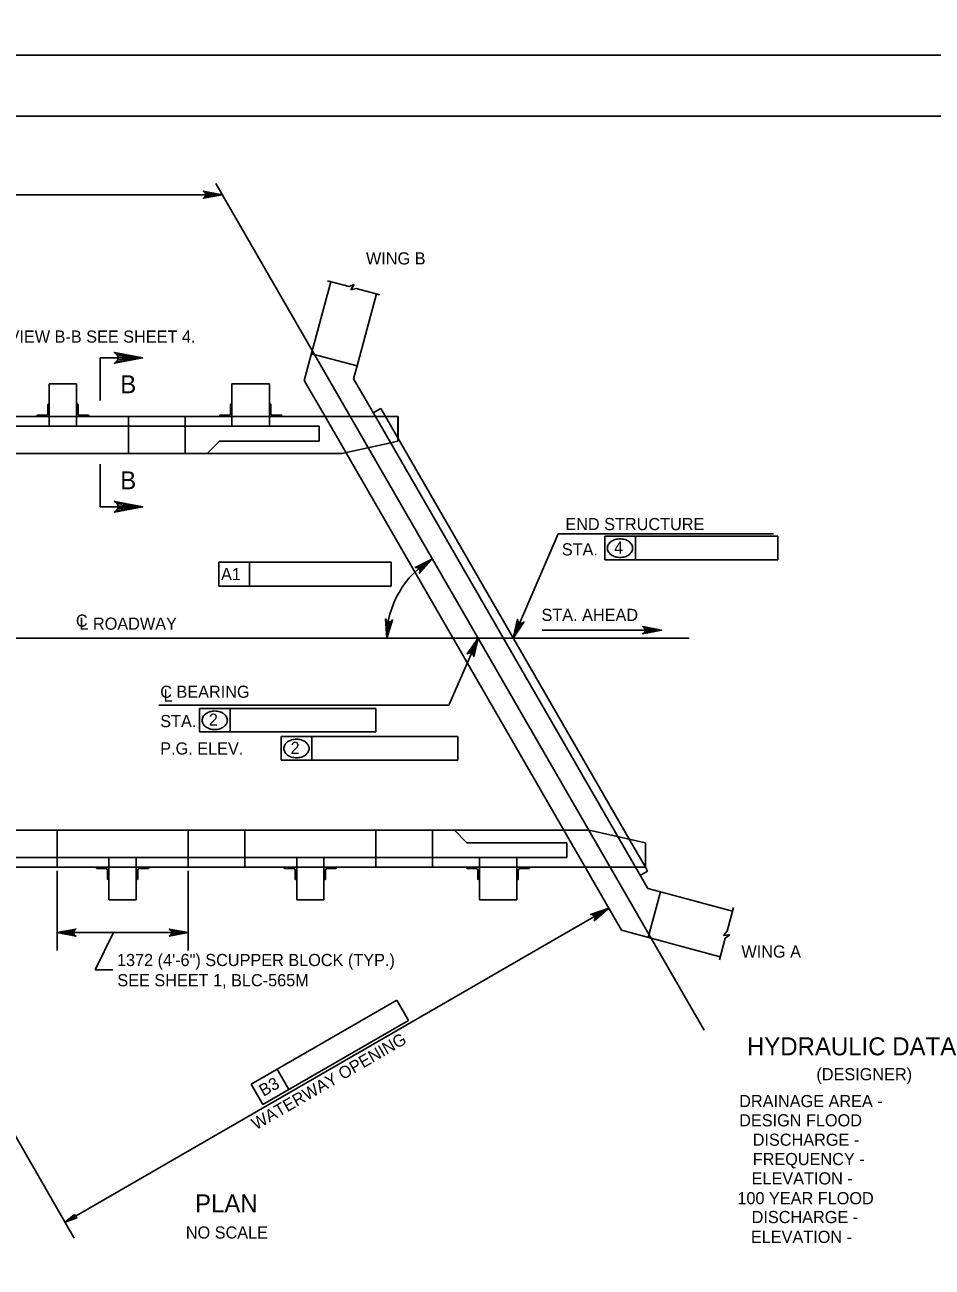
# Model space of a CAD drawing. Extents: x 638175 to 640495, y 294277 to 298435.
# Drawn here: x 638663 to 638887, y 296948.4 to 297255 of the extents above; entities that cross this region are included whole.
import ezdxf

# ---------------------------------------------------------------- set-up
doc = ezdxf.new("R2010")
doc.units = 0
for name, color, linetype in [('2', 7, 'Continuous'), ('3', 7, 'Continuous'), ('4', 7, 'Continuous'), ('PLT-BNDY', 7, 'Continuous')]:
    doc.layers.add(name, color=color, linetype=linetype)

msp = doc.modelspace()

# ---------------------------------------------------------------- linework, layer by layer
at = {"layer": '2'}
for p, q in [((638475.46, 297232.46), (639261.46, 297232.46)), ((638732.01, 297167.17), (638738.55, 297191.57)), ((638745.03, 297170.77), (638749.79, 297188.56)), ((638681.61, 297172.77), (638681.61, 297162.29)), ((638681.61, 297172.77), (638692.1, 297172.77)), ((638745.03, 297170.77), (638733.78, 297173.78)), ((638744.18, 297167.62), (638745.03, 297170.77)), ((638675.77, 297166.36), (638669.04, 297166.36)), ((638675.77, 297166.36), (638669.04, 297166.36)), ((638675.77, 297166.36), (638669.04, 297166.36)), ((638669.04, 297166.36), (638669.04, 297155.88)), ((638675.77, 297166.36), (638675.77, 297155.88)), ((638723.39, 297166.36), (638714.15, 297166.36)), ((638714.15, 297166.36), (638714.15, 297155.88)), ((638723.39, 297166.36), (638723.39, 297155.88)), ((638732.01, 297167.17), (638737.15, 297158.27)), ((638744.18, 297167.62), (638749.58, 297158.27)), ((638668.68, 297161.18), (638668.68, 297159)), ((638668.86, 297161.36), (638669.04, 297161.36)), ((638669.04, 297161.36), (638669.04, 297158.27)), ((638675.95, 297161.36), (638675.77, 297161.36)), ((638675.77, 297161.36), (638675.77, 297158.27)), ((638676.13, 297161.18), (638676.13, 297159)), ((638713.79, 297161.18), (638713.79, 297159)), ((638713.97, 297161.36), (638714.15, 297161.36)), ((638714.15, 297161.36), (638714.15, 297158.27)), ((638723.57, 297161.36), (638723.39, 297161.36)), ((638723.39, 297161.36), (638723.39, 297158.27)), ((638723.75, 297161.18), (638723.75, 297159)), ((638750.87, 297160.29), (638749.03, 297159.22)), ((638750.87, 297160.29), (638752.04, 297158.27)), ((638543.27, 297158.27), (638755.15, 297158.27)), ((638608.04, 297158.27), (638755.13, 297158.27)), ((638667.79, 297158.27), (638664.7, 297158.27)), ((638665.95, 297158.45), (638665.95, 297158.27)), ((638669.04, 297158.27), (638665.95, 297158.27)), ((638666.13, 297158.63), (638668.32, 297158.63)), ((638677.02, 297158.27), (638667.79, 297158.27)), ((638677.02, 297158.27), (638667.79, 297158.27)), ((638675.77, 297158.27), (638669.04, 297158.27)), ((638675.77, 297158.27), (638678.86, 297158.27)), ((638678.68, 297158.63), (638676.5, 297158.63)), ((638677.02, 297158.27), (638680.12, 297158.27)), ((638678.86, 297158.45), (638678.86, 297158.27)), ((638688.58, 297158.27), (638688.58, 297149.15)), ((638702.6, 297158.27), (638702.6, 297149.15)), ((638711.06, 297158.45), (638711.06, 297158.27)), ((638714.15, 297158.27), (638711.06, 297158.27)), ((638711.24, 297158.63), (638713.42, 297158.63)), ((638723.39, 297158.27), (638714.15, 297158.27)), ((638723.39, 297158.27), (638726.48, 297158.27)), ((638726.3, 297158.63), (638724.12, 297158.63)), ((638726.48, 297158.45), (638726.48, 297158.27)), ((638737.15, 297158.27), (638801.34, 297047.1)), ((638749.58, 297158.27), (638813.77, 297047.1)), ((638752.04, 297158.27), (638755.15, 297152.88)), ((638755.13, 297152.89), (638755.13, 297158.27)), ((638755.13, 297158.27), (638755.13, 297152.24)), ((638755.15, 297152.89), (638755.15, 297158.27)), ((638735.71, 297155.88), (638607.87, 297155.88)), ((638735.71, 297155.88), (638735.71, 297152.24)), ((638707.98, 297149.15), (638711.07, 297152.24)), ((638735.71, 297152.24), (638711.07, 297152.24)), ((638752.96, 297151.76), (638741.28, 297149.15)), ((638755.13, 297152.24), (638752.96, 297151.76)), ((638755.15, 297152.88), (638812.49, 297053.57)), ((638590.42, 297149.15), (638741.28, 297149.15)), ((638707.98, 297149.15), (638691.82, 297149.15)), ((638681.61, 297136.04), (638681.61, 297146.53)), ((638681.61, 297136.04), (638692.1, 297136.04)), ((638651.51, 297056.22), (638667.67, 297056.22)), ((638651.51, 297056.22), (638802.37, 297056.22)), ((638670.96, 297047.1), (638670.96, 297056.22)), ((638703.3, 297047.1), (638703.3, 297056.22)), ((638717.33, 297047.1), (638717.33, 297056.22)), ((638769.07, 297056.22), (638748.29, 297056.22)), ((638749.67, 297047.1), (638749.67, 297056.22)), ((638763.69, 297047.1), (638763.69, 297056.22)), ((638769.07, 297056.22), (638772.16, 297053.13)), ((638814.05, 297053.61), (638802.37, 297056.22)), ((638796.8, 297053.13), (638772.16, 297053.13)), ((638796.8, 297049.49), (638796.8, 297053.13)), ((638812.49, 297053.57), (638816.22, 297047.1)), ((638816.22, 297053.13), (638814.05, 297053.61)), ((638816.22, 297047.1), (638816.22, 297053.13)), ((638816.22, 297052.48), (638816.22, 297047.1)), ((638623.78, 297049.49), (638668.96, 297049.49)), ((638669.05, 297047.1), (638645.34, 297047.1)), ((638796.8, 297049.49), (638668.96, 297049.49)), ((638669.13, 297047.1), (638816.22, 297047.1)), ((638680.68, 297046.92), (638680.68, 297047.1)), ((638683.77, 297047.1), (638680.68, 297047.1)), ((638680.86, 297046.73), (638683.04, 297046.73)), ((638683.77, 297039.01), (638683.77, 297049.49)), ((638690.5, 297047.1), (638683.77, 297047.1)), ((638683.77, 297044.01), (638683.77, 297047.1)), ((638690.5, 297039.01), (638690.5, 297049.49)), ((638690.5, 297044.01), (638690.5, 297047.1)), ((638690.5, 297047.1), (638693.59, 297047.1)), ((638693.4, 297046.73), (638691.22, 297046.73)), ((638693.59, 297046.92), (638693.59, 297047.1)), ((638727.04, 297046.92), (638727.04, 297047.1)), ((638730.13, 297047.1), (638727.04, 297047.1)), ((638727.22, 297046.73), (638729.4, 297046.73)), ((638738.11, 297047.1), (638728.88, 297047.1)), ((638730.13, 297039.01), (638730.13, 297049.49)), ((638736.86, 297047.1), (638730.13, 297047.1)), ((638730.13, 297044.01), (638730.13, 297047.1)), ((638736.86, 297039.01), (638736.86, 297049.49)), ((638736.86, 297044.01), (638736.86, 297047.1)), ((638736.86, 297047.1), (638739.95, 297047.1)), ((638739.77, 297046.73), (638737.59, 297046.73)), ((638739.95, 297046.92), (638739.95, 297047.1)), ((638772.15, 297046.92), (638772.15, 297047.1)), ((638775.24, 297047.1), (638772.15, 297047.1)), ((638772.33, 297046.73), (638774.51, 297046.73)), ((638775.24, 297039.01), (638775.24, 297049.49)), ((638784.48, 297047.1), (638775.24, 297047.1)), ((638775.24, 297044.01), (638775.24, 297047.1)), ((638784.48, 297039.01), (638784.48, 297049.49)), ((638784.48, 297044.01), (638784.48, 297047.1)), ((638784.48, 297047.1), (638787.57, 297047.1)), ((638787.39, 297046.73), (638785.21, 297046.73)), ((638787.57, 297046.92), (638787.57, 297047.1)), ((638810.33, 297031.52), (638801.34, 297047.1)), ((638813.77, 297047.1), (638816.8, 297041.84)), ((638816.22, 297047.1), (638816.78, 297046.14)), ((638816.22, 297047.1), (638816.78, 297046.14)), ((638683.4, 297044.19), (638683.4, 297046.37)), ((638683.59, 297044.01), (638683.77, 297044.01)), ((638690.68, 297044.01), (638690.5, 297044.01)), ((638690.86, 297044.19), (638690.86, 297046.37)), ((638729.77, 297044.19), (638729.77, 297046.37)), ((638729.95, 297044.01), (638730.13, 297044.01)), ((638737.04, 297044.01), (638736.86, 297044.01)), ((638737.22, 297044.19), (638737.22, 297046.37)), ((638774.88, 297044.19), (638774.88, 297046.37)), ((638775.06, 297044.01), (638775.24, 297044.01)), ((638784.66, 297044.01), (638784.48, 297044.01)), ((638784.84, 297044.19), (638784.84, 297046.37)), ((638816.78, 297046.14), (638814.93, 297045.07)), ((638816.8, 297041.84), (638819.95, 297041)), ((638819.95, 297041), (638816.94, 297029.75)), ((638819.95, 297041), (638837.74, 297036.23)), ((638690.5, 297039.01), (638683.77, 297039.01)), ((638736.86, 297039.01), (638730.13, 297039.01)), ((638736.86, 297039.01), (638730.13, 297039.01)), ((638784.48, 297039.01), (638775.24, 297039.01)), ((638810.33, 297031.52), (638834.73, 297024.98))]:
    msp.add_line(p, q, dxfattribs=at)
for points in [[(638692.1, 297172.77), (638685.1, 297171.46), (638685.64, 297171.83), (638685.92, 297172.3), (638686, 297172.77), (638685.92, 297173.24), (638685.64, 297173.71), (638685.1, 297174.08), (638692.1, 297172.77), (638685.64, 297173.71), (638685.92, 297173.24), (638692.1, 297172.77), (638686, 297172.77), (638685.92, 297172.3), (638692.1, 297172.77), (638685.64, 297171.83)], [(638692.1, 297136.04), (638685.1, 297137.35), (638685.64, 297136.98), (638685.92, 297136.51), (638686, 297136.04), (638685.92, 297135.57), (638685.64, 297135.1), (638685.1, 297134.73), (638692.1, 297136.04), (638685.64, 297135.1), (638685.92, 297135.57), (638692.1, 297136.04), (638686, 297136.04), (638685.92, 297136.51), (638692.1, 297136.04), (638685.64, 297136.98)]]:
    msp.add_lwpolyline(points, dxfattribs=at)
for centre, radius, start, end in [((638668.86, 297161.18), 0.182, 90, 179.9984), ((638675.95, 297161.18), 0.182, 0.0016, 90), ((638713.97, 297161.18), 0.182, 90, 179.9984), ((638723.57, 297161.18), 0.182, 0.0016, 90), ((638666.13, 297158.45), 0.182, 90, 179.9984), ((638668.32, 297159), 0.364, 270, 359.9984), ((638676.5, 297159), 0.364, 180.0016, 270), ((638678.68, 297158.45), 0.182, 0.0016, 90), ((638711.24, 297158.45), 0.182, 90, 179.9984), ((638713.42, 297159), 0.364, 270, 359.9984), ((638724.12, 297159), 0.364, 180.0016, 270), ((638726.3, 297158.45), 0.182, 0.0016, 90), ((638680.86, 297046.92), 0.182, 180.0016, 270), ((638683.04, 297046.37), 0.364, 0.0016, 90), ((638691.22, 297046.37), 0.364, 90, 179.9984), ((638693.4, 297046.92), 0.182, 270, 359.9984), ((638727.22, 297046.92), 0.182, 180.0016, 270), ((638729.4, 297046.37), 0.364, 0.0016, 90), ((638737.59, 297046.37), 0.364, 90, 179.9984), ((638739.77, 297046.92), 0.182, 270, 359.9984), ((638772.33, 297046.92), 0.182, 180.0016, 270), ((638774.51, 297046.37), 0.364, 0.0016, 90), ((638785.21, 297046.37), 0.364, 90, 179.9984), ((638787.39, 297046.92), 0.182, 270, 359.9984), ((638683.59, 297044.19), 0.182, 180.0016, 270), ((638690.68, 297044.19), 0.182, 270, 359.9984), ((638729.95, 297044.19), 0.182, 180.0016, 270), ((638737.04, 297044.19), 0.182, 270, 359.9984), ((638775.06, 297044.19), 0.182, 180.0016, 270), ((638784.66, 297044.19), 0.182, 270, 359.9984)]:
    msp.add_arc(centre, radius, start, end, dxfattribs=at)
at = {"layer": '3'}
for p, q in [((638710.15, 297215.8), (638830.78, 297006.86)), ((638520.34, 297213.03), (638711.75, 297213.03)), ((638743.09, 297190.36), (638737.76, 297191.79)), ((638743.09, 297190.36), (638744.35, 297190.89)), ((638744.35, 297190.89), (638743.49, 297189.59)), ((638743.49, 297189.59), (638744.83, 297189.89)), ((638750.66, 297188.33), (638744.83, 297189.89)), ((638837.98, 297037.1), (638836.41, 297031.26)), ((638835.49, 297030.25), (638836.41, 297031.26)), ((638835.95, 297029.53), (638834.52, 297024.19)), ((638837.04, 297030.35), (638835.49, 297030.25)), ((638835.95, 297029.53), (638837.04, 297030.35))]:
    msp.add_line(p, q, dxfattribs=at)
at = {"layer": '4'}
for p, q in [((638783.58, 297103.64), (638794.7, 297129.36)), ((638794.7, 297129.36), (638847.88, 297129.36)), ((638806.18, 297128.74), (638813.76, 297128.74)), ((638806.18, 297122.97), (638806.18, 297128.74)), ((638813.76, 297122.97), (638813.76, 297128.74)), ((638813.76, 297128.74), (638848.94, 297128.74)), ((638848.94, 297128.74), (638848.94, 297122.97)), ((638710.94, 297122.37), (638710.93, 297116.46)), ((638710.94, 297122.37), (638718.5, 297122.37)), ((638718.49, 297116.46), (638718.5, 297122.37)), ((638718.5, 297122.37), (638753.46, 297122.37)), ((638753.45, 297116.46), (638753.46, 297122.37)), ((638806.18, 297122.97), (638848.94, 297122.97)), ((638710.93, 297116.46), (638753.45, 297116.46)), ((638820.24, 297105.57), (638790.72, 297105.57)), ((638541.99, 297103.64), (638827.01, 297103.64)), ((638774.91, 297103.64), (638767.73, 297087.03)), ((638767.73, 297087.03), (638696.05, 297087.03)), ((638706.1, 297086.27), (638713.68, 297086.27)), ((638706.1, 297080.5), (638706.1, 297086.27)), ((638713.68, 297080.5), (638713.68, 297086.27)), ((638713.68, 297086.27), (638749.69, 297086.27)), ((638749.69, 297086.27), (638749.69, 297080.5)), ((638706.1, 297080.5), (638749.69, 297080.5)), ((638726.29, 297073.53), (638726.29, 297079.3)), ((638726.29, 297079.3), (638733.87, 297079.3)), ((638733.87, 297073.53), (638733.87, 297079.3)), ((638733.87, 297079.3), (638769.88, 297079.3)), ((638769.88, 297079.3), (638769.88, 297073.53)), ((638726.29, 297073.53), (638769.88, 297073.53)), ((638670.96, 297046.17), (638670.96, 297026.53)), ((638703.3, 297046.17), (638703.3, 297026.53)), ((638628.28, 297036.84), (638675.2, 296955.57)), ((638672.95, 296959.47), (638807.18, 297036.97)), ((638670.96, 297030.96), (638703.3, 297030.96)), ((638684.92, 297030.96), (638680.33, 297021.73)), ((638680.33, 297021.73), (638684.76, 297021.73)), ((638725.28, 296997.22), (638754.86, 297014.26)), ((638754.86, 297014.26), (638757.73, 297009.27)), ((638757.73, 297009.27), (638721.75, 296988.54)), ((638718.87, 296993.54), (638725.28, 296997.22)), ((638728.16, 296992.23), (638725.28, 296997.22)), ((638721.75, 296988.54), (638718.87, 296993.54))]:
    msp.add_line(p, q, dxfattribs=at)
for points in [[(638711.75, 297213.03), (638707.09, 297212.16), (638707.45, 297212.4), (638707.63, 297212.72), (638707.69, 297213.03), (638707.63, 297213.34), (638707.45, 297213.65), (638707.09, 297213.9), (638711.75, 297213.03), (638707.45, 297213.65), (638707.63, 297213.34), (638711.75, 297213.03), (638707.69, 297213.03), (638707.63, 297212.72), (638711.75, 297213.03), (638707.45, 297212.4)], [(638763.64, 297123.15), (638760.47, 297119.63), (638760.6, 297120.05), (638760.56, 297120.41), (638760.41, 297120.69), (638760.18, 297120.9), (638759.84, 297121.04), (638759.41, 297121.02), (638763.64, 297123.15), (638759.84, 297121.04), (638760.18, 297120.9), (638763.64, 297123.15), (638760.41, 297120.69), (638760.56, 297120.41), (638763.64, 297123.15), (638760.6, 297120.05)], [(638752.37, 297103.62), (638752.07, 297108.35), (638752.28, 297107.97), (638752.56, 297107.75), (638752.87, 297107.65), (638753.18, 297107.67), (638753.52, 297107.82), (638753.81, 297108.14), (638752.37, 297103.62), (638753.52, 297107.82), (638753.18, 297107.67), (638752.37, 297103.62), (638752.87, 297107.65), (638752.56, 297107.75), (638752.37, 297103.62), (638752.28, 297107.97)], [(638783.58, 297103.64), (638784.63, 297108.26), (638784.71, 297107.83), (638784.93, 297107.54), (638785.19, 297107.37), (638785.5, 297107.29), (638785.86, 297107.34), (638786.23, 297107.57), (638783.58, 297103.64), (638785.86, 297107.34), (638785.5, 297107.29), (638783.58, 297103.64), (638785.19, 297107.37), (638784.93, 297107.54), (638783.58, 297103.64), (638784.71, 297107.83)], [(638820.24, 297105.57), (638815.58, 297104.7), (638815.94, 297104.94), (638816.13, 297105.26), (638816.18, 297105.57), (638816.13, 297105.88), (638815.94, 297106.19), (638815.58, 297106.44), (638820.24, 297105.57), (638815.94, 297106.19), (638816.13, 297105.88), (638820.24, 297105.57), (638816.18, 297105.57), (638816.13, 297105.26), (638820.24, 297105.57), (638815.94, 297104.94)], [(638774.91, 297103.64), (638773.86, 297099.01), (638773.77, 297099.44), (638773.56, 297099.73), (638773.29, 297099.91), (638772.99, 297099.98), (638772.63, 297099.94), (638772.26, 297099.71), (638774.91, 297103.64), (638772.63, 297099.94), (638772.99, 297099.98), (638774.91, 297103.64), (638773.29, 297099.91), (638773.56, 297099.73), (638774.91, 297103.64), (638773.77, 297099.44)], [(638807.18, 297036.97), (638803.58, 297033.88), (638803.77, 297034.27), (638803.78, 297034.64), (638803.67, 297034.93), (638803.46, 297035.18), (638803.15, 297035.36), (638802.71, 297035.39), (638807.18, 297036.97), (638803.15, 297035.36), (638803.46, 297035.18), (638807.18, 297036.97), (638803.67, 297034.93), (638803.78, 297034.64), (638807.18, 297036.97), (638803.77, 297034.27)], [(638670.96, 297030.96), (638675.62, 297031.83), (638675.26, 297031.58), (638675.08, 297031.27), (638675.03, 297030.96), (638675.08, 297030.65), (638675.26, 297030.33), (638675.62, 297030.09), (638670.96, 297030.96), (638675.26, 297030.33), (638675.08, 297030.65), (638670.96, 297030.96), (638675.03, 297030.96), (638675.08, 297031.27), (638670.96, 297030.96), (638675.26, 297031.58)], [(638703.3, 297030.96), (638698.64, 297030.09), (638699, 297030.33), (638699.19, 297030.65), (638699.24, 297030.96), (638699.19, 297031.27), (638699, 297031.58), (638698.64, 297031.83), (638703.3, 297030.96), (638699, 297031.58), (638699.19, 297031.27), (638703.3, 297030.96), (638699.24, 297030.96), (638699.19, 297030.65), (638703.3, 297030.96), (638699, 297030.33)]]:
    msp.add_lwpolyline(points, dxfattribs=at)
for points in [[(638784.3, 297106.54), (638785.21, 297106.15), (638783.58, 297103.64)], [(638817.36, 297106.05), (638817.36, 297105.09), (638820.24, 297105.57)], [(638774.19, 297100.73), (638773.28, 297101.12), (638774.91, 297103.64)], [(638804.34, 297035.9), (638804.84, 297035.03), (638807.18, 297036.97)], [(638673.92, 297031.45), (638673.92, 297030.47), (638670.96, 297030.96)], [(638700.35, 297031.45), (638700.35, 297030.47), (638703.3, 297030.96)], [(638675.3, 296961.4), (638675.8, 296960.53), (638672.95, 296959.47)]]:
    msp.add_lwpolyline(points, close=True, dxfattribs=at)
for centre, radius, start, end in [((638808.56, 297125.81), 1.71, 150.6308, 180), ((638809.24, 297125.43), 2.49, 126.3544, 150.6308), ((638809.68, 297124.83), 3.23, 106.9552, 126.3544), ((638809.97, 297123.88), 4.22, 90, 106.9552), ((638809.97, 297123.88), 4.22, 73.0448, 90), ((638810.26, 297124.83), 3.23, 53.6456, 73.0448), ((638810.7, 297125.43), 2.49, 29.3692, 53.6456), ((638811.37, 297125.81), 1.71, 0, 29.3692), ((638774.91, 297103.64), 22.54, 119.9992, 179.9979), ((638808.56, 297125.81), 1.71, 180, 209.3692), ((638809.24, 297126.19), 2.49, 209.3692, 233.6456), ((638809.68, 297126.79), 3.23, 233.6456, 253.0448), ((638809.97, 297127.74), 4.22, 253.0448, 270), ((638809.97, 297127.74), 4.22, 270, 286.9552), ((638810.26, 297126.79), 3.23, 286.9552, 306.3544), ((638810.7, 297126.19), 2.49, 306.3544, 330.6308), ((638811.37, 297125.81), 1.71, 330.6308, 0), ((638708.48, 297083.34), 1.71, 150.6308, 180), ((638708.48, 297083.34), 1.71, 180, 209.3692), ((638709.15, 297082.96), 2.49, 126.3544, 150.6308), ((638709.6, 297082.36), 3.23, 106.9552, 126.3544), ((638709.89, 297081.41), 4.22, 90, 106.9552), ((638709.89, 297081.41), 4.22, 73.0448, 90), ((638710.17, 297082.36), 3.23, 53.6456, 73.0448), ((638710.62, 297082.96), 2.49, 29.3692, 53.6456), ((638711.29, 297083.34), 1.71, 0, 29.3692), ((638711.29, 297083.34), 1.71, 330.6308, 0), ((638709.15, 297083.72), 2.49, 209.3692, 233.6456), ((638709.6, 297084.32), 3.23, 233.6456, 253.0448), ((638709.89, 297085.27), 4.22, 253.0448, 270), ((638709.89, 297085.27), 4.22, 270, 286.9552), ((638710.17, 297084.32), 3.23, 286.9552, 306.3544), ((638710.62, 297083.72), 2.49, 306.3544, 330.6308), ((638728.67, 297076.37), 1.71, 150.6308, 180), ((638729.34, 297075.99), 2.49, 126.3544, 150.6308), ((638729.79, 297075.39), 3.23, 106.9552, 126.3544), ((638730.07, 297074.45), 4.22, 90, 106.9552), ((638730.07, 297074.45), 4.22, 73.0448, 90), ((638730.36, 297075.39), 3.23, 53.6456, 73.0448), ((638730.8, 297075.99), 2.49, 29.3692, 53.6456), ((638731.48, 297076.37), 1.71, 0, 29.3692), ((638728.67, 297076.37), 1.71, 180, 209.3692), ((638729.34, 297076.75), 2.49, 209.3692, 233.6456), ((638729.79, 297077.35), 3.23, 233.6456, 253.0448), ((638730.07, 297078.3), 4.22, 253.0448, 270), ((638730.07, 297078.3), 4.22, 270, 286.9552), ((638730.36, 297077.35), 3.23, 286.9552, 306.3544), ((638730.8, 297076.75), 2.49, 306.3544, 330.6308), ((638731.48, 297076.37), 1.71, 330.6308, 0)]:
    msp.add_arc(centre, radius, start, end, dxfattribs=at)
at = {"layer": 'PLT-BNDY'}
for points in [[(638435.46, 297841.46), (639276.46, 297841.46), (639276.46, 297247.46), (638435.46, 297247.46)], [(638435.46, 297247.46), (639276.46, 297247.46), (639276.46, 296653.46), (638435.46, 296653.46)]]:
    msp.add_lwpolyline(points, close=True, dxfattribs=at)

# ---------------------------------------------------------------- texts
at = {"layer": '4'}
for s, height, p in [('WING B', 3, (638747.23, 297195.82)), ('FOR VIEW B-B SEE SHEET 4.', 3, (638649.4, 297176.53)), ('B', 4.43, (638686.55, 297140.34)), ('END STRUCTURE', 3, (638796.46, 297130.26)), ('STA.', 3, (638795.59, 297124.02)), ('4', 3, (638808.51, 297124.46)), ('STA. AHEAD', 3, (638790.57, 297107.85)), ('C', 3, (638675.61, 297106.43)), ('L ROADWAY', 3, (638676.47, 297105.69)), ('C BEARING', 3, (638696.43, 297088.88)), ('L', 3, (638697.25, 297087.96)), ('STA.', 3, (638696.43, 297081.64)), ('2', 3, (638708.43, 297081.99)), ('P.G. ELEV.', 3, (638696.43, 297074.89)), ('2', 3, (638728.62, 297075.02)), ('1372 (4\'-6") SCUPPER BLOCK (TYP.)', 3, (638685.74, 297022.68)), ('WING A', 3, (638839.94, 297024.76)), ('SEE SHEET 1, BLC-565M', 3, (638685.84, 297017.69)), ('HYDRAULIC DATA', 4.4292, (638841.31, 297000.66)), ('(DESIGNER)', 3, (638858.45, 296994.5)), ('DRAINAGE AREA - ', 3, (638839.39, 296987.87)), ('DESIGN FLOOD  ', 3, (638839.39, 296983.12)), ('   DISCHARGE - ', 3, (638839.39, 296978.33)), ('   FREQUENCY - ', 3, (638839.39, 296973.56)), ('   ELEVATION - ', 3, (638839.12, 296968.79)), ('100 YEAR FLOOD', 3, (638838.94, 296963.9)), ('PLAN', 4.429, (638705.02, 296961.91)), ('   DISCHARGE - ', 3, (638839.12, 296959.25)), ('NO SCALE', 3, (638702.75, 296955.44)), ('   ELEVATION - ', 3, (638838.94, 296954.36))]:
    msp.add_text(s, height=height, dxfattribs=at).set_placement(p)
for s, height, rotation, p in [('B', 4.43, 360, (638686.55, 297164.05)), ('A1', 3, 359.9382, (638711.45, 297117.92)), ('WATERWAY OPENING', 3, 30, (638720.08, 296982.14)), ('B3', 3, 29.9438, (638721.92, 296990.39))]:
    msp.add_text(s, height=height, rotation=rotation, dxfattribs=at).set_placement(p)

doc.saveas('drawing.dxf')
